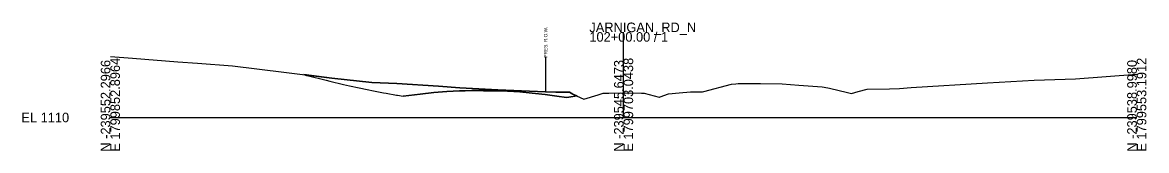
# Model space of a CAD drawing. Extents: x 214513 to 217151, y 214739 to 216780.
# Drawn here: x 216822.7 to 217151.2, y 214738.7 to 214776.2 of the extents above; entities that cross this region are included whole.
import ezdxf

# ---------------------------------------------------------------- set-up
doc = ezdxf.new("R2010")
doc.units = 0
for name, color, linetype in [('DESIGN - DRAINAGE - Special Ditches', 7, 'Continuous'), ('DESIGN - EARTHWORK - Shapes', 7, 'Continuous'), ('DESIGN - TRANSPORTATION - Text', 7, 'Continuous'), ('Section', 7, 'Continuous'), ('SURVEY - DTM GRAPHICS - Triangles', 7, 'Continuous'), ('SURVEY - PROPERTY - ROW Lines', 7, 'Continuous'), ('XSCell', 7, 'Continuous')]:
    doc.layers.add(name, color=color, linetype=linetype)

msp = doc.modelspace()

# ---------------------------------------------------------------- linework, layer by layer
at = {"layer": 'DESIGN - DRAINAGE - Special Ditches'}
for points in [[(216904.87, 214760.91), (216905.7, 214760.69), (216905.85, 214760.65), (216911.41, 214759.27), (216912.47, 214759), (216916.48, 214758.07), (216918.28, 214757.65), (216921.07, 214757.04), (216923.46, 214756.52), (216925.27, 214756.16), (216928.16, 214755.59), (216928.98, 214755.44), (216931.99, 214754.9), (216932.25, 214754.86), (216933.95, 214754.59)], [(216981.67, 214754.2), (216978.81, 214754.64), (216975.44, 214755.08), (216971.65, 214755.51), (216967.99, 214755.84), (216964.43, 214756.07), (216960.93, 214756.22), (216957.45, 214756.28), (216953.95, 214756.26), (216950.39, 214756.15), (216946.74, 214755.95), (216942.94, 214755.65), (216938.95, 214755.24), (216935.57, 214754.82), (216933.95, 214754.59)], [(216966.27, 214755.95), (216964.43, 214755.98), (216960.93, 214756.04), (216957.45, 214756.1), (216953.95, 214756.16), (216952.04, 214756.2), (216953.95, 214756.26), (216957.45, 214756.28), (216960.93, 214756.22), (216964.43, 214756.07), (216966.27, 214755.95)], [(216984.75, 214754.68), (216982.36, 214754.3), (216981.67, 214754.2)]]:
    msp.add_lwpolyline(points, dxfattribs=at)
at = {"layer": 'DESIGN - EARTHWORK - Shapes'}
for p, q in [((216952.04, 214756.2), (216953.95, 214756.26)), ((216975.57, 214755.91), (216975.57, 214755.91))]:
    msp.add_line(p, q, dxfattribs=at)
for points in [[(216975.57, 214755.91), (216961.57, 214756.46), (216950.46, 214757.04), (216944.28, 214757.57), (216932.07, 214758.35), (216924.75, 214758.58), (216913.07, 214759.91), (216904.87, 214760.91)], [(216904.87, 214760.91), (216905.7, 214760.69), (216905.85, 214760.65), (216911.41, 214759.27), (216912.47, 214759), (216916.48, 214758.07), (216918.28, 214757.65), (216921.07, 214757.04), (216923.46, 214756.52), (216925.27, 214756.16), (216928.16, 214755.59), (216928.98, 214755.44), (216931.99, 214754.9), (216932.25, 214754.86), (216933.95, 214754.59)], [(216933.95, 214754.59), (216935.57, 214754.82), (216938.95, 214755.24), (216942.94, 214755.65), (216946.74, 214755.95), (216950.39, 214756.15), (216952.04, 214756.2)], [(216952.04, 214756.2), (216952.04, 214756.2)], [(216953.95, 214756.26), (216957.45, 214756.28), (216960.93, 214756.22), (216964.43, 214756.07), (216966.27, 214755.95), (216967.99, 214755.84)], [(216967.99, 214755.84), (216971.65, 214755.51), (216975.44, 214755.08), (216978.81, 214754.64), (216981.67, 214754.2)], [(216984.71, 214754.67), (216983.53, 214755.23), (216982.51, 214755.79), (216978.59, 214755.82), (216975.58, 214755.91), (216975.57, 214755.91)], [(216975.57, 214755.91), (216975.57, 214755.91)], [(216981.67, 214754.2), (216982.36, 214754.3), (216984.71, 214754.67)]]:
    msp.add_lwpolyline(points, dxfattribs=at)
at = {"layer": 'SURVEY - DTM GRAPHICS - Triangles'}
msp.add_lwpolyline([(216848.36, 214766.26), (216854.79, 214765.76), (216868.04, 214764.62), (216873.87, 214764.3), (216884.05, 214763.46), (216899.04, 214761.62), (216913.07, 214759.91), (216924.75, 214758.58), (216932.07, 214758.35), (216944.28, 214757.57), (216950.46, 214757.04), (216961.57, 214756.46), (216975.58, 214755.91), (216978.59, 214755.82), (216982.51, 214755.79), (216983.53, 214755.23), (216986.76, 214753.71), (216990.98, 214754.98), (216992.36, 214755.45), (216994.05, 214755.5), (216998.85, 214755.6), (217003.59, 214755.48), (217004.4, 214755.45), (217008.72, 214754.33), (217008.84, 214754.29), (217009.07, 214754.38), (217011.45, 214755.31), (217014.62, 214755.62), (217017.9, 214755.86), (217021.17, 214755.9), (217021.47, 214755.9), (217021.85, 214755.99), (217029.89, 214758.11), (217031.16, 214758.24), (217031.87, 214758.35), (217038.36, 214758.28), (217044.69, 214758.21), (217049.62, 214757.85), (217056.39, 214757.37), (217058.05, 214757.07), (217058.52, 214756.96), (217063.82, 214755.67), (217064.98, 214755.37), (217066.91, 214755.93), (217069.56, 214756.66), (217076.05, 214756.78), (217079.04, 214756.83), (217082.43, 214757.11), (217104.75, 214758.48), (217118.41, 214759.27), (217130.47, 214759.65), (217148.36, 214761.1)], dxfattribs=at)
at = {"layer": 'SURVEY - PROPERTY - ROW Lines'}
msp.add_lwpolyline([(216975.57, 214765.91), (216975.57, 214755.91)], dxfattribs=at)
at = {"layer": 'XSCell'}
for p, q in [((216998.36, 214748.36), (216998.36, 214773.36)), ((216848.36, 214748.36), (216998.36, 214748.36)), ((216998.36, 214748.36), (217148.36, 214748.36))]:
    msp.add_line(p, q, dxfattribs=at)

# ---------------------------------------------------------------- texts
at = {"layer": 'DESIGN - TRANSPORTATION - Text'}
msp.add_text('PRES. R.O.W.', height=1, rotation=90, dxfattribs=at).set_placement((216976.07, 214765.91))
at = {"layer": 'Section'}
msp.add_text('-', height=0.0001, dxfattribs=at).set_placement((216848.36, 214748.36))
at = {"layer": 'XSCell'}
for s, p in [('JARNIGAN_RD_N', (216988.36, 214773.36)), ('102+00.00 / 1', (216988.36, 214770.56)), ('EL 1110', (216822.36, 214746.96))]:
    msp.add_text(s, height=2.8, dxfattribs=at).set_placement(p)
for s, p in [('N -239552.2966', (216848.36, 214738.36)), ('E 1799852.8964', (216851.16, 214738.36)), ('N -239545.6473', (216998.36, 214738.36)), ('E 1799703.0438', (217001.16, 214738.36)), ('N -239538.9980', (217148.36, 214738.36)), ('E 1799553.1912', (217151.16, 214738.36))]:
    msp.add_text(s, height=2.8, rotation=90, dxfattribs=at).set_placement(p)

doc.saveas('drawing.dxf')
